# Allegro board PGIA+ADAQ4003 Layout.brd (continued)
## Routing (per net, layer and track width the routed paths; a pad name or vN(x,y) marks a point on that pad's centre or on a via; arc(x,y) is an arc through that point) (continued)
UNNAMED_4_CNBNC5P_I403_CNTR: length 14.1
  TOP w0.406: R27.1 15.41,4.93 R10.1 ; R27.1 VIN+.1 J2.1 J4.1 ; R27.1 15.41,4.9 15.41,4.19
UNNAMED_4_DIOSCHOTTKY_I374_N: length 3.3
  TOP w0.406: D3.A 16.93,13.17 R9.2 13.8,13.17 D4.C
UNNAMED_4_DIOSCHOTTKY_I376_N: length 3.3
  TOP w0.406: D5.A 16.93,7.12 R10.2 13.8,7.12 D6.C
UNNAMED_4_NCTESTPAD_I380_N1: length 8.4
  TOP w0.203: U5.16 v1(25.99,6.17)
  BOTTOM w0.203: v1(25.99,6.17) 27,6.17 28.4,4.78 TP_A1.1 R31.1
UNNAMED_4_RESNET8P4RV5_I204_N6: length 0.7
  TOP w0.203: RN2.7 RN2.6
UNNAMED_4_RESNET8P4RV7_I203_N6: length 0.7
  TOP w0.203: RN3.7 RN3.6
UNNAMED_4_RESNET8P4RV7_I206_N6: length 0.7
  TOP w0.203: RN1.7 RN1.6
UNNAMED_7_ADLTC1983X_I198_C: length 1.8
  BOTTOM w0.406: C49.1 52.55,11.32 U6.3
UNNAMED_7_ADLTC1983X_I198_C_1: length 1.8
  BOTTOM w0.406: C49.2 52.55,8.7 U6.4
UNNAMED_7_ADLTC1983X_I198_SHDNN: length 5.9
  BOTTOM w0.406: U6.6 U6.1 49.75,11.32 C46.2 50.42,13.55 R40.2
UNNAMED_7_ADLTC1983X_I198_VOUT: length 2.4
  BOTTOM w0.406: R44.1 50.7,12.33 U6.2
UNNAMED_7_ADP5070_I184_COMP1: length 2.6
  BOTTOM w0.201: C51.1 R52.1 70.07,12.05 U4.6
UNNAMED_7_ADP5070_I184_COMP2: length 2.3
  BOTTOM w0.201: C52.1 R55.1 70.7,10.05 U4.10
UNNAMED_7_ADP5070_I184_EN1: length 10.7
  BOTTOM w0.201: 73.96,12.17 71.12,12.17 70.5,11.55 U4.7
  BOTTOM w0.203: R80.2 75.3,7.39 74.4,8.29 R81.1 74.4,11.73 73.96,12.17
UNNAMED_7_ADP5070_I184_EN2: length 7.9
  TOP w0.203: v1(73.46,9.83) 71.89,9.83 v2(71.17,10.55)
  BOTTOM w0.203: v1(73.46,9.83) 73.46,9.21 R36.1 73.69,8.98 73.69,8.41 72.45,7.17 R35.2 ; v2(71.17,10.55) U4.9
UNNAMED_7_ADP5070_I184_FB1: length 2.5
  BOTTOM w0.201: U4.5 68.61,14.01 R58.1
  BOTTOM w0.3: R58.1 R54.2
UNNAMED_7_ADP5070_I184_FB2: length 2.8
  BOTTOM w0.254: U4.11 68.61,8.21 69.26,7.56
  BOTTOM w0.3: 69.26,7.56 R42.1 R53.1
UNNAMED_7_ADP5070_I184_PVIN1: length 6.3
  BOTTOM w0.201: 66.6,9.03 66,9.03
  BOTTOM w0.203: U4.15 66.6,9.03 66.6,8.33 66.47,8.2 65.99,8.2
  BOTTOM w0.254: 64.77,10.54 64.78,10.55 U4.17 U4.16
  BOTTOM w0.305: 64.82,10.05 U4.16 65.59,9.64
  BOTTOM w0.508: v1(73.66,5.83) 73.45,6.04 R35.1 73.47,6.65 R80.1
  vias: v1(65.02,9.39) v1(65.71,9.39) v1(72.42,16.57) v1(72.39,15.76) v1(72.39,14.97)
UNNAMED_7_ADP5070_I184_SS: length 4.1
  BOTTOM w0.201: U4.8 70.86,11.05 71.31,11.5 R41.2
UNNAMED_7_ADP5070_I184_SW2: length 2.7
  BOTTOM w0.203: U4.18 64.36,11.05 64.03,10.72 64.03,9.75
UNNAMED_7_ADP5070_I184_VREF: length 3.2
  BOTTOM w0.201: U4.12 68.11,7.44
  BOTTOM w0.3: R42.2 69.02,6.54 C28.1 68.11,7.44
UNNAMED_7_ADP5070_I184_VREG: length 1.8
  BOTTOM w0.201: U4.14 67.11,7.44
  BOTTOM w0.3: 67.11,7.44 C7.2
UNNAMED_7_ADP7185_I188_SENSE: length 3.3
  BOTTOM w0.203: U7.2 U7.1 50.09,17.21 C43.1 49.32,15.22 R43.2
UNNAMED_7_ADP7185_I188_VA: length 2.8
  BOTTOM w0.203: C45.1 C48.1 49.8,18.21 U7.3
UNNAMED_7_ADP7185_I188_VAFB: length 1.5
  BOTTOM w0.203: C48.2 49.48,18.71 U7.4
UNNAMED_7_ADP7185_I188_VREG: length 1.3
  BOTTOM w0.203: C56.1 53.93,17.71 U7.7
UNNAMED_7_CAP_I43_N1: length 0.9
  BOTTOM w0.5: R55.2 72.68,9.78 C55.1
UNNAMED_7_CAP_I44_N1: length 0.8
  BOTTOM w0.5: R52.2 C54.1
UNNAMED_7_CAP_I164_N1: length 3.9
  TOP w0.203: v2(40.33,17.91) 40.33,17.88 39.97,17.52 v1(38.22,17.52)
  BOTTOM w0.203: C15.1 v1(38.22,17.52)
  BOTTOM w0.254: U8.11 v2(40.33,17.91)
UNNAMED_7_CAP_I164_N2: length 13.2
  TOP w0.203: v1(39.12,12.65) 39.12,13.84 36.4,16.56 v1(35.33,16.56)
  BOTTOM w0.203: C15.2 37.34,15.25 C17.2 35.98,15 35.33,15.65 v1(35.33,16.56) ; v1(39.12,12.65) R22.1 39.84,13.18 39.63,13.39 39.06,13.39 38.83,13.61 U8.7
UNNAMED_7_CAP_I165_N1: length 1.5
  BOTTOM w0.203: C14.1 40.83,12.71 U8.3
UNNAMED_7_CAP_I175_N2: length 1.5
  BOTTOM w0.203: U3.5 38.93,7.38 C12.2
UNNAMED_7_CAP_I176_N2: length 1.7
  BOTTOM w0.203: U3.1 38.93,2.91 C13.2
UNNAMED_7_CAP_I210_N2: length 5.3
  BOTTOM w0.203: 69.01,16.12 69.01,16.2 C41.2
  BOTTOM w0.399: R65.1 69.7,17.7 69.02,17.03 69.02,16.21 ; 69.01,16.12 R58.2 69.02,15.32 69.02,16.21 ; 69.02,16.21 C41.2
  BOTTOM w0.508: v1(68.79,18.67) 69.18,18.67 69.76,18.1 R65.1
  vias: v1(58.32,15.75) v1(59.18,15.75)
UNNAMED_7_CAP_I211_N2: length 3.2
  BOTTOM w0.406: C42.2 70.73,5.61 v1(70.94,5.83) ; C42.2 70.28,5.63 R53.2 ; C42.2 70.31,5.61 70.31,5.05 70.6,4.76 R66.1
  vias: v1(57.43,11.16) v1(57.4,10.5)
UNNAMED_7_DIOLED_I227_P: length 1.6
  TOP w0.203: DS1.A R34.2
UNNAMED_7_LINLT3023_I170_IN: length 5.4
  BOTTOM w0.203: 44.37,4.88 R17.1 45.4,3.96 R13.2 ; 44.37,4.88 U3.8 ; 44.37,4.88 R16.1
UNNAMED_7_LINLT3023_I170_SHDN1N: length 1.5
  BOTTOM w0.203: U3.7 43.03,5.38 R16.2
UNNAMED_7_LINLT3023_I170_SHDN2N: length 1.5
  BOTTOM w0.203: R17.2 42.95,4.38 U3.9
UNNAMED_7_LINLT3032_I158_INN1: length 5
  BOTTOM w0.203: U8.6 39.33,15.48 U8.PAD2 39.33,15.82 U8.9
  BOTTOM w0.254: U8.9 39.33,18.06 R15.2
UNNAMED_7_LINLT3032_I158_SHDNNN: length 3.7
  BOTTOM w0.254: U8.10 39.83,17.59 39.8,17.63 39.8,18.19 R18.2 40.87,18.34 40.87,17.65 40.83,17.62 U8.12
UNNAMED_7_RES_I159_N2: length 0.8
  BOTTOM w0.254: U8.14 41.83,17.98
X1: length 10.8
  TOP w0.203: RN2.2 28.55,6.7 v1(28.55,7.35) RN2.1 ; v1(23.7,11.1) 23.7,11.71 23.39,12.02 U5.5
  BOTTOM w0.203: v1(23.7,11.1) 24.8,11.1 v1(28.55,7.35)
  BOTTOM w0.305: C38.1 v1(28.55,7.35)
X2: length 9.9
  TOP w0.203: v1(27.1,10.79) 27.44,11.14 v1(28.55,11.14) ; U5.6 v1(22.74,11.79) ; v1(28.55,11.14) RN3.1 ; v1(28.55,11.14) 28.55,10.49 RN3.2
  BOTTOM w0.203: v1(27.1,10.79) 25.7,10.79 24.71,11.79 v1(22.74,11.79)
  BOTTOM w0.305: v1(28.55,11.14) C35.1
X3: length 14.8
  TOP w0.203: U5.7 22.09,11.03 22.91,10.21 24.74,10.21 26.59,12.06 26.59,14.63 26.88,14.92 RN1.1 v1(28.91,14.92) 28.91,14.47 28.71,14.27 RN1.2
  BOTTOM w0.305: v1(28.91,14.92) C30.1
Y1: length 11.5
  TOP w0.203: RN2.3 28.55,6.05 v1(28.55,5.4) ; v1(28.55,5.4) RN2.4 ; v1(28.55,5.4) 27.08,5.4 26.62,5.86 26.62,8.56 26.42,8.76 23.59,8.76 23.39,8.55 U5.12
  BOTTOM w0.305: C36.1 v1(28.55,5.4)
Y2: length 9.5
  TOP w0.203: v1(28.55,9.18) 28.54,9.19 23.11,9.19 22.74,8.82 U5.11 ; v1(28.55,9.18) 28.55,9.83 RN3.3 ; v1(28.55,9.18) RN3.4
  BOTTOM w0.305: v1(28.55,9.18) C34.1
Y3: length 12.3
  TOP w0.203: U5.10 22.09,9.06 22.73,9.7 24.97,9.7 27.12,11.86 27.12,12.7 27.39,12.97 v1(28.55,12.97) ; v1(28.55,12.97) RN1.4 ; v1(28.55,12.97) 28.55,13.62 RN1.3
  BOTTOM w0.305: v1(28.55,12.97) C31.1

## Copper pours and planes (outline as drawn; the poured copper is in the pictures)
1V8 on BOTTOM (solid shape): 48.44,3.35 48.44,2.97 48.21,2.74 46.53,2.74 46.53,3.61 48.18,3.61
1V8 on BOTTOM: 51.55,6.77 52.74,6.77 53,6.52 53,3.8 53.68,3.11 55.08,3.11 55.31,2.88 55.31,1.97 51.9,1.97 51.24,2.63 51.24,6.46
1V8 on L3_PWR: 42.43,16.5 42.93,16.5 44.46,14.96 51.61,14.96 53.39,13.18 53.39,6.83 52.79,6.24 51.52,6.24 51.37,6.39 51.37,13.07 50.48,13.96 44.28,13.96 42.23,16.01 42.23,16.29
1V8 on L3_PWR: 47.52,3.02 47.96,3.45 48.39,3.45 49.82,2.02 52.79,2.02 53.29,2.51 55.24,2.51 55.63,2.13 55.63,1 47.52,1
3V3EXT on BOTTOM: 79.38,18.8 80.64,18.8 82.3,17.15 82.3,15.76 78.36,15.76 78.36,17.15 79.38,17.15
3V3IN on BOTTOM: 76,19.55 78.64,19.55 78.64,17.91 77.6,17.91 77.6,17.53 76,17.53
3V3IN on L3_PWR: 27.05,19.56 44.96,19.56 45.21,19.3 45.21,18.29 45.89,17.61 55.13,17.61 57.93,14.82 64.85,14.82 65.41,15.38 69.27,15.38 69.27,19.32 77.75,19.32 77.75,17.23 76.68,17.23 76.38,17.54 72.31,17.54 71.58,16.8 71.58,14.9 70.13,13.45 57.8,13.45 54.98,16.27 45.59,16.27 43.47,18.39 34.54,18.39 33.15,16.99 27.05,16.99
5V5 on BOTTOM (solid shape): 48.44,7.21 48.44,6.76 48.23,6.55 46.51,6.55 46.51,7.39 48.26,7.39
5V5 on L3_PWR: 47.74,13.78 48.91,13.78 50.34,12.35 50.34,6.84 51.5,5.68 61.72,5.68 61.72,10.33 62.13,10.73 63.25,10.73 63.25,5.61 64.68,4.18 64.68,1.04 56.41,1.04 56.31,1.14 56.31,1.98 55.29,3 53.41,3 52.85,2.44 50.06,2.44 48.49,4.01 46.81,4.01 46.61,3.81 46.61,1.42 46.25,1.07 44.3,1.07 44.2,1.17 44.2,5.03 47.74,5.03
AGND on TOP: 0.76,19.56 84.31,19.56 84.31,0.76 0.76,0.76 0.76,4.45 4.37,4.45 4.37,5.38 0.76,5.38 0.76,14.94 4.5,14.94 4.5,15.87 0.76,15.87 ; 30 cut-outs
AGND on BOTTOM: 79.38,19.56 84.31,19.56 84.31,0.76 0.76,0.76 0.76,19.56 45.21,19.56 45.21,18.8 46.23,18.8 46.23,19.56 46.61,19.56 46.61,18.67 47.12,18.67 47.12,19.56 48.39,19.56 48.39,18.67 47.5,18.67 47.5,18.03 48.3,18.03 48.3,17.87 49.67,17.87 49.67,18.58 49.28,18.58 49.28,19.56 74.8,19.56 74.8,17.53 74.17,17.53 74.17,14.48 75.18,14.48 75.18,14.73 75.56,14.73 75.56,16.64 77.47,16.64 77.47,14.99 82.42,14.99 82.42,17.02 82.04,17.02 82.04,16.64 77.85,16.64 77.85,17.65 75.82,17.65 75.82,19.56 78.74,19.56 78.74,17.15 79.38,17.15 ; 51 cut-outs
AGND on L2_GND: 0.76,19.56 84.31,19.56 84.31,0.76 0.76,0.76 ; 1 cut-out
AGND on L3_PWR: 78.89,19.56 84.31,19.56 84.31,0.76 74.55,0.76 74.55,16.59 78.89,16.59
AGND on L3_PWR: 0.77,19.38 25.75,19.38 26.16,18.97 26.16,17.12 13,17.12 8.84,12.96 8.84,3.4 27.97,3.4 27.97,9.96 28.41,10.4 35.33,10.4 35.33,7.58 44.28,7.58 44.37,7.49 44.37,5.31 44.3,5.23 43.69,5.23 43.69,1 0.77,1
P15V on TOP: 16.59,11.94 16.59,8.46 17.7,8.46 18.29,9.04 18.29,11.48 17.83,11.94
P15V on L3_PWR: 33.77,14.03 44.46,14.03 47,11.49 47,5.75 46.69,5.44 45.07,5.44 45.07,11.01 43.75,12.33 38.99,12.33 38.99,12.41 35.33,12.41 35.33,11.79 34.68,11.14 27.24,11.14 27.1,11 27.1,3.63 16.05,3.63 14.1,5.59 14.1,10.88 14.74,11.53 22.81,11.53 24.69,13.41 33.15,13.41
P16V on BOTTOM: 44.07,19.56 45.85,19.56 46.1,19.3 46.1,18.54 45.85,18.29 43.94,18.29 43.94,19.43
P16V on L3_PWR: 45.44,19.49 67.69,19.49 67.69,16.8 65.1,16.8 64.03,17.87 46.16,17.87 45.44,18.59
N3V on BOTTOM: 51.09,18.28 52.03,18.28 52.03,17.41 52.79,17.41 52.96,17.25 52.96,14.4 53.59,14.4 53.72,14.27 53.72,13.54 52.03,13.54 51.09,14.48
N15V on TOP: 12.4,11.51 12.4,9.12 13,8.51 14.15,8.51 14.15,11.94 12.83,11.94
N15V on L3_PWR: 13.66,16.41 38.35,16.41 38.49,16.27 38.49,15.74 37.59,14.83 33.97,14.83 32.85,13.72 23.88,13.72 22.5,12.34 14.3,12.34 13.34,11.38 13.34,4.53 9.75,4.53 9.75,12.5
N16V on L3_PWR: 43.05,18.1 45.14,16.01 54.44,16.01 56.38,14.08 56.38,10.25 56.83,9.79 58.36,9.79 58.82,10.26 58.82,11.28 59.41,11.86 64.47,11.86 64.47,7.65 66.14,7.65 67.11,6.68 67.11,2.83 70.84,2.83 70.84,1.03 65.76,1.04 65.51,1.04 65.25,1.3 65.25,4.57 63.55,6.27 63.55,10.96 61.8,10.96 61.37,10.53 61.37,6.16 54.55,6.16 54.03,6.68 54.03,13.37 52.16,15.24 44.59,15.24 43.03,16.8 35.83,16.8 35.83,17.97 35.95,18.1
UNNAMED_7_ADP5070_I184_INBK on BOTTOM (solid shape): 66.85,14.35 66.72,14.22 66.72,12.7 66.47,12.7 66.47,13.21 65.96,13.72 65.96,16.51 66.85,16.51
UNNAMED_7_ADP5070_I184_PVIN1 on BOTTOM: 71.88,19.55 74.68,19.55 74.68,17.53 74.17,17.53 74.17,14.6 72.4,14.6 71.88,15.13
UNNAMED_7_ADP5070_I184_PVIN1 on BOTTOM: 64.64,10.72 65.78,10.72 65.78,9.84 65.79,9.84 65.79,9.69 66.24,9.69 66.24,9.32 66.67,9.32 66.67,8.56 66.5,8.38 66.5,8.46 66.25,8.71 66.25,7.83 66.16,7.74 66.16,7.75 65.71,7.29 65.1,7.29 64.64,7.75 ; 1 cut-out
UNNAMED_7_ADP5070_I184_PVIN1 on L3_PWR: 64.77,9.69 64.77,8.28 64.8,8.26 66.7,8.26 67.69,7.26 67.69,3.44 74.19,3.44 74.19,17.21 72.52,17.21 71.97,16.66 71.97,5.6 71.16,4.79 69.16,4.79 69.16,8.23 67.69,9.7 67.67,9.68 66.01,9.68 66.01,9.69
UNNAMED_7_ADP5070_I184_SW1 on BOTTOM (solid shape): 65.38,12.57 65.78,12.17 65.78,11.91 65.17,11.91 64.89,12.19 64.89,12.83 63.88,13.84 62.61,13.84 62.61,14.73 63.88,14.73 64.77,15.62 65.38,15.62
UNNAMED_7_ADP5070_I184_SW2 on BOTTOM: 59.05,9.09 59.05,8.25 59.18,8.13 59.18,6.48 59.94,6.48 59.94,7.49 60.2,7.75 62.87,7.75 64.26,9.14 64.26,10.42 64.13,10.54 64.01,10.54 62.56,9.09
UNNAMED_7_CAP_I29_N2 on BOTTOM: 54.23,7.49 58.04,7.49 58.04,6.22 59.94,6.22 59.94,3.94 56.26,3.94 56.26,5.97 55.63,5.97 54.61,6.98 54.23,6.98
UNNAMED_7_CAP_I46_N2 on BOTTOM: 55.46,16.31 62.48,16.31 62.48,15.62 63.5,15.62 63.5,16.89 62.87,17.53 62.87,18.58 55.46,18.58
UNNAMED_7_CAP_I165_N2 on BOTTOM: 42.93,15.75 44.2,15.75 44.2,14.86 43.69,14.86 43.69,12.19 41.78,12.19 41.78,14.35 42.93,14.35
UNNAMED_7_CAP_I210_N2 on BOTTOM: 55.88,15.49 55.88,14.98 57.15,13.72 57.15,12.57 57.66,12.57 57.66,13.39 57.99,13.72 60.96,13.72 60.96,15.24 60.2,15.24 59.44,16 57.91,16 57.4,15.49
UNNAMED_7_CAP_I210_N2 on L3_PWR: 67.97,19.3 69.04,19.3 69.04,15.62 65.16,15.62 64.59,15.05 58.52,15.05 57.92,15.65 57.92,16.52 67.97,16.52
UNNAMED_7_CAP_I211_N2 on BOTTOM: 57.15,11.43 57.91,11.43 57.91,8.47 54.1,8.47 54.1,10.29 56.52,10.29 56.52,11.18 57.15,11.18
UNNAMED_7_CAP_I211_N2 on L3_PWR: 57.4,13.14 65.02,13.14 65.05,13.12 71.3,13.12 71.3,12.69 71.32,12.69 71.32,5.57 69.77,5.57 69.77,8.61 68.17,10.21 66.71,10.21 66.71,10.24 64.87,10.24 64.87,12.1 59.35,12.1 58.54,11.3 58.54,10.4 58.37,10.22 57,10.22 57,12.79 57.05,12.79
UNNAMED_7_RES_I159_N2 on BOTTOM (solid shape): 43.05,18.29 42.16,18.29 42.04,18.16 42.04,17.78 41.91,17.65 41.78,17.65 41.53,17.91 41.53,19.18 43.05,19.18

Small or netless copper shapes (teardrops, artwork), in the pictures only: 1 on BOTTOM

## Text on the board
Ref Des/Assembly Bottom: A | C
Ref Des/Silkscreen Bottom: SECONDARY SIDE | 08-065908 | REV B Z | C | A
User.Comments: 5.    SINGULATE BOARDS AFTER ASSEMBLY PROCESS. | 6.    INSTALL JUMPER SHUNTS (M028265)  ON THE FOLLOWING CONNECTORS: | A. JA0 | B. JA1
Ref Des/Assembly Top: A | C
Ref Des/Silkscreen Top: REV B Z | 08-065908 | PRIMARY SIDE | EVP-PMB0002 PGIA+ADAQ4003 | C | 3V3IN | A
PAGE_OUTLINE: N.GARLITOS | M.VALE | K.JABATAN | M.YAN | 24SEP20 | B | CHANGES PER ECR-110924 | 14OCT22 | EVP-PMB0002 PGIA+ADAQ4003
DIMENSION: 30 | VCUT | DIA MAX/SEE NOTE15 | +/-10% | 0.062" | PCB | 0.025" +/-4 MILS | REMAINING UNCUT | GROOVE DETAILS FOR V-CUT REQUIREMENT | - | " " | (REF) | NON-PLATED: +/- 2 MILS
User.11: 1 | 2 | 3
User.12: 2 | 3 | 1
User.15: PER IPC-4552 LATEST VERSION | 16.    BOARDS TO BE SHIPPED IN ARRAY.
User.17: L2 GND | 08-      -07
User.18: L3 PWR | 08-      -08
User.45: FIGURE | SIZE | 6.0 | 8.0 | 10.0 | 15.0 | 16.0 | 30.0 | 40.0 | 45.0 | 60.0 | 125.0 | DRILL CHART: TOP to BOTTOM | FINISHED HOLES IN MILS | PLATED | NON-PLATED | QTY | 24 | 30 | 226 | 16 | 8 | 4 | 12 | 10 | TOLERANCE/NOTES
